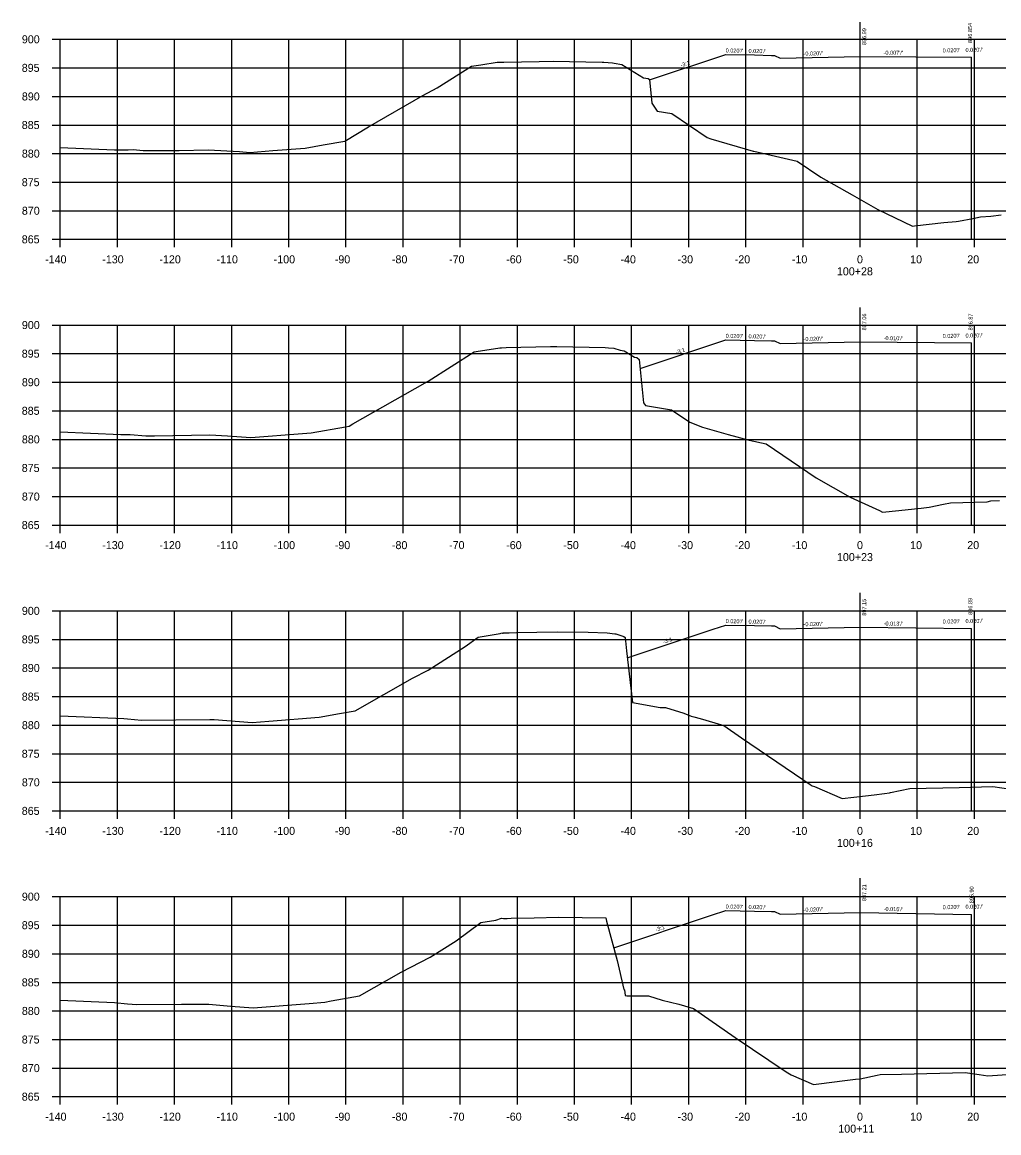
# Model space of a CAD drawing. Extents: x 1098669 to 1198896, y 698679 to 704410.
# Drawn here: x 1110744.5 to 1110915.5, y 704215.9 to 704410.2 of the extents above; entities that cross this region are included whole.
import ezdxf

# ---------------------------------------------------------------- set-up
doc = ezdxf.new("R2010")
doc.units = 0
for name, color, linetype in [('R_Axis', 7, 'Continuous'), ('R_Axis Annot', 7, 'Continuous'), ('R_Fin Surface', 7, 'Continuous'), ('R_Grid', 7, 'Continuous'), ('R_No Plot', 7, 'Continuous'), ('R_Xsect Elev', 7, 'Continuous'), ('R_Xsect Slope', 7, 'Continuous')]:
    doc.layers.add(name, color=color, linetype=linetype)

msp = doc.modelspace()

# ---------------------------------------------------------------- linework, layer by layer
at = {"layer": 'R_Axis'}
for p, q in [((1110749.8, 704407.22), (1110751.2, 704407.22)), ((1110751.2, 704372.22), (1110751.2, 704407.22)), ((1110749.8, 704402.22), (1110751.2, 704402.22)), ((1110749.8, 704397.22), (1110751.2, 704397.22)), ((1110749.8, 704392.22), (1110751.2, 704392.22)), ((1110749.8, 704387.22), (1110751.2, 704387.22)), ((1110749.8, 704382.22), (1110751.2, 704382.22)), ((1110749.8, 704377.22), (1110751.2, 704377.22)), ((1110749.8, 704372.22), (1110751.2, 704372.22)), ((1110751.2, 704372.22), (1111031.2, 704372.22)), ((1110751.2, 704370.82), (1110751.2, 704372.22)), ((1110761.2, 704370.82), (1110761.2, 704372.22)), ((1110771.2, 704370.82), (1110771.2, 704372.22)), ((1110781.2, 704370.82), (1110781.2, 704372.22)), ((1110791.2, 704370.82), (1110791.2, 704372.22)), ((1110801.2, 704370.82), (1110801.2, 704372.22)), ((1110811.2, 704370.82), (1110811.2, 704372.22)), ((1110821.2, 704370.82), (1110821.2, 704372.22)), ((1110831.2, 704370.82), (1110831.2, 704372.22)), ((1110841.2, 704370.82), (1110841.2, 704372.22)), ((1110851.2, 704370.82), (1110851.2, 704372.22)), ((1110861.2, 704370.82), (1110861.2, 704372.22)), ((1110871.2, 704370.82), (1110871.2, 704372.22)), ((1110881.2, 704370.82), (1110881.2, 704372.22)), ((1110891.2, 704370.82), (1110891.2, 704372.22)), ((1110901.2, 704370.82), (1110901.2, 704372.22)), ((1110911.2, 704370.82), (1110911.2, 704372.22)), ((1110749.8, 704357.22), (1110751.2, 704357.22)), ((1110751.2, 704322.22), (1110751.2, 704357.22)), ((1110749.8, 704352.22), (1110751.2, 704352.22)), ((1110749.8, 704347.22), (1110751.2, 704347.22)), ((1110749.8, 704342.22), (1110751.2, 704342.22)), ((1110749.8, 704337.22), (1110751.2, 704337.22)), ((1110749.8, 704332.22), (1110751.2, 704332.22)), ((1110749.8, 704327.22), (1110751.2, 704327.22)), ((1110749.8, 704322.22), (1110751.2, 704322.22)), ((1110751.2, 704322.22), (1111031.2, 704322.22)), ((1110751.2, 704320.82), (1110751.2, 704322.22)), ((1110761.2, 704320.82), (1110761.2, 704322.22)), ((1110771.2, 704320.82), (1110771.2, 704322.22)), ((1110781.2, 704320.82), (1110781.2, 704322.22)), ((1110791.2, 704320.82), (1110791.2, 704322.22)), ((1110801.2, 704320.82), (1110801.2, 704322.22)), ((1110811.2, 704320.82), (1110811.2, 704322.22)), ((1110821.2, 704320.82), (1110821.2, 704322.22)), ((1110831.2, 704320.82), (1110831.2, 704322.22)), ((1110841.2, 704320.82), (1110841.2, 704322.22)), ((1110851.2, 704320.82), (1110851.2, 704322.22)), ((1110861.2, 704320.82), (1110861.2, 704322.22)), ((1110871.2, 704320.82), (1110871.2, 704322.22)), ((1110881.2, 704320.82), (1110881.2, 704322.22)), ((1110891.2, 704320.82), (1110891.2, 704322.22)), ((1110901.2, 704320.82), (1110901.2, 704322.22)), ((1110911.2, 704320.82), (1110911.2, 704322.22)), ((1110749.8, 704307.22), (1110751.2, 704307.22)), ((1110751.2, 704272.22), (1110751.2, 704307.22)), ((1110749.8, 704302.22), (1110751.2, 704302.22)), ((1110749.8, 704297.22), (1110751.2, 704297.22)), ((1110749.8, 704292.22), (1110751.2, 704292.22)), ((1110749.8, 704287.22), (1110751.2, 704287.22)), ((1110749.8, 704282.22), (1110751.2, 704282.22)), ((1110749.8, 704277.22), (1110751.2, 704277.22)), ((1110749.8, 704272.22), (1110751.2, 704272.22)), ((1110751.2, 704272.22), (1111031.2, 704272.22)), ((1110751.2, 704270.82), (1110751.2, 704272.22)), ((1110761.2, 704270.82), (1110761.2, 704272.22)), ((1110771.2, 704270.82), (1110771.2, 704272.22)), ((1110781.2, 704270.82), (1110781.2, 704272.22)), ((1110791.2, 704270.82), (1110791.2, 704272.22)), ((1110801.2, 704270.82), (1110801.2, 704272.22)), ((1110811.2, 704270.82), (1110811.2, 704272.22)), ((1110821.2, 704270.82), (1110821.2, 704272.22)), ((1110831.2, 704270.82), (1110831.2, 704272.22)), ((1110841.2, 704270.82), (1110841.2, 704272.22)), ((1110851.2, 704270.82), (1110851.2, 704272.22)), ((1110861.2, 704270.82), (1110861.2, 704272.22)), ((1110871.2, 704270.82), (1110871.2, 704272.22)), ((1110881.2, 704270.82), (1110881.2, 704272.22)), ((1110891.2, 704270.82), (1110891.2, 704272.22)), ((1110901.2, 704270.82), (1110901.2, 704272.22)), ((1110911.2, 704270.82), (1110911.2, 704272.22)), ((1110749.8, 704257.22), (1110751.2, 704257.22)), ((1110751.2, 704222.22), (1110751.2, 704257.22)), ((1110749.8, 704252.22), (1110751.2, 704252.22)), ((1110749.8, 704247.22), (1110751.2, 704247.22)), ((1110749.8, 704242.22), (1110751.2, 704242.22)), ((1110749.8, 704237.22), (1110751.2, 704237.22)), ((1110749.8, 704232.22), (1110751.2, 704232.22)), ((1110749.8, 704227.22), (1110751.2, 704227.22)), ((1110749.8, 704222.22), (1110751.2, 704222.22)), ((1110751.2, 704222.22), (1111031.2, 704222.22)), ((1110751.2, 704220.82), (1110751.2, 704222.22)), ((1110761.2, 704220.82), (1110761.2, 704222.22)), ((1110771.2, 704220.82), (1110771.2, 704222.22)), ((1110781.2, 704220.82), (1110781.2, 704222.22)), ((1110791.2, 704220.82), (1110791.2, 704222.22)), ((1110801.2, 704220.82), (1110801.2, 704222.22)), ((1110811.2, 704220.82), (1110811.2, 704222.22)), ((1110821.2, 704220.82), (1110821.2, 704222.22)), ((1110831.2, 704220.82), (1110831.2, 704222.22)), ((1110841.2, 704220.82), (1110841.2, 704222.22)), ((1110851.2, 704220.82), (1110851.2, 704222.22)), ((1110861.2, 704220.82), (1110861.2, 704222.22)), ((1110871.2, 704220.82), (1110871.2, 704222.22)), ((1110881.2, 704220.82), (1110881.2, 704222.22)), ((1110891.2, 704220.82), (1110891.2, 704222.22)), ((1110901.2, 704220.82), (1110901.2, 704222.22)), ((1110911.2, 704220.82), (1110911.2, 704222.22))]:
    msp.add_line(p, q, dxfattribs=at)
at = {"layer": 'R_Fin Surface'}
for points in [[(1110854.34, 704400.12), (1110867.7, 704404.57), (1110872.7, 704404.47), (1110875.7, 704404.41), (1110876.2, 704404.41), (1110877.2, 704403.93), (1110891.2, 704404.21), (1110910.7, 704404.07)], [(1110852.68, 704349.63), (1110867.7, 704354.64), (1110872.7, 704354.54), (1110875.7, 704354.48), (1110876.2, 704354.48), (1110877.2, 704354), (1110891.2, 704354.28), (1110910.7, 704354.09)], [(1110850.43, 704298.98), (1110865.47, 704303.99), (1110867.7, 704304.73), (1110872.7, 704304.63), (1110875.7, 704304.57), (1110876.2, 704304.57), (1110877.2, 704304.09), (1110891.2, 704304.37), (1110910.7, 704304.11)], [(1110848.08, 704248.25), (1110865.18, 704253.95), (1110867.7, 704254.79), (1110872.7, 704254.69), (1110875.7, 704254.63), (1110876.2, 704254.63), (1110877.2, 704254.15), (1110891.2, 704254.43), (1110910.7, 704254.12)]]:
    msp.add_lwpolyline(points, dxfattribs=at)
at = {"layer": 'R_Grid'}
for p, q in [((1110751.2, 704407.22), (1111031.2, 704407.22)), ((1110751.2, 704372.22), (1110751.2, 704407.22)), ((1110761.2, 704372.22), (1110761.2, 704407.22)), ((1110771.2, 704372.22), (1110771.2, 704407.22)), ((1110781.2, 704372.22), (1110781.2, 704407.22)), ((1110791.2, 704372.22), (1110791.2, 704407.22)), ((1110801.2, 704372.22), (1110801.2, 704407.22)), ((1110811.2, 704372.22), (1110811.2, 704407.22)), ((1110821.2, 704372.22), (1110821.2, 704407.22)), ((1110831.2, 704372.22), (1110831.2, 704407.22)), ((1110841.2, 704372.22), (1110841.2, 704407.22)), ((1110851.2, 704372.22), (1110851.2, 704407.22)), ((1110861.2, 704372.22), (1110861.2, 704407.22)), ((1110871.2, 704372.22), (1110871.2, 704407.22)), ((1110881.2, 704372.22), (1110881.2, 704407.22)), ((1110891.2, 704372.22), (1110891.2, 704407.22)), ((1110901.2, 704372.22), (1110901.2, 704407.22)), ((1110911.2, 704372.22), (1110911.2, 704407.22)), ((1110910.7, 704372.22), (1110910.7, 704404.07)), ((1110751.2, 704402.22), (1111031.2, 704402.22)), ((1110751.2, 704397.22), (1111031.2, 704397.22)), ((1110751.2, 704392.22), (1111031.2, 704392.22)), ((1110751.2, 704387.22), (1111031.2, 704387.22)), ((1110751.2, 704382.22), (1111031.2, 704382.22)), ((1110751.2, 704377.22), (1111031.2, 704377.22)), ((1110751.2, 704372.22), (1111031.2, 704372.22)), ((1110751.2, 704357.22), (1111031.2, 704357.22)), ((1110751.2, 704322.22), (1110751.2, 704357.22)), ((1110761.2, 704322.22), (1110761.2, 704357.22)), ((1110771.2, 704322.22), (1110771.2, 704357.22)), ((1110781.2, 704322.22), (1110781.2, 704357.22)), ((1110791.2, 704322.22), (1110791.2, 704357.22)), ((1110801.2, 704322.22), (1110801.2, 704357.22)), ((1110811.2, 704322.22), (1110811.2, 704357.22)), ((1110821.2, 704322.22), (1110821.2, 704357.22)), ((1110831.2, 704322.22), (1110831.2, 704357.22)), ((1110841.2, 704322.22), (1110841.2, 704357.22)), ((1110851.2, 704322.22), (1110851.2, 704357.22)), ((1110861.2, 704322.22), (1110861.2, 704357.22)), ((1110871.2, 704322.22), (1110871.2, 704357.22)), ((1110881.2, 704322.22), (1110881.2, 704357.22)), ((1110891.2, 704322.22), (1110891.2, 704357.22)), ((1110901.2, 704322.22), (1110901.2, 704357.22)), ((1110911.2, 704322.22), (1110911.2, 704357.22)), ((1110910.7, 704322.22), (1110910.7, 704354.09)), ((1110751.2, 704352.22), (1111031.2, 704352.22)), ((1110751.2, 704347.22), (1111031.2, 704347.22)), ((1110751.2, 704342.22), (1111031.2, 704342.22)), ((1110751.2, 704337.22), (1111031.2, 704337.22)), ((1110751.2, 704332.22), (1111031.2, 704332.22)), ((1110751.2, 704327.22), (1111031.2, 704327.22)), ((1110751.2, 704322.22), (1111031.2, 704322.22)), ((1110751.2, 704307.22), (1111031.2, 704307.22)), ((1110751.2, 704272.22), (1110751.2, 704307.22)), ((1110761.2, 704272.22), (1110761.2, 704307.22)), ((1110771.2, 704272.22), (1110771.2, 704307.22)), ((1110781.2, 704272.22), (1110781.2, 704307.22)), ((1110791.2, 704272.22), (1110791.2, 704307.22)), ((1110801.2, 704272.22), (1110801.2, 704307.22)), ((1110811.2, 704272.22), (1110811.2, 704307.22)), ((1110821.2, 704272.22), (1110821.2, 704307.22)), ((1110831.2, 704272.22), (1110831.2, 704307.22)), ((1110841.2, 704272.22), (1110841.2, 704307.22)), ((1110851.2, 704272.22), (1110851.2, 704307.22)), ((1110861.2, 704272.22), (1110861.2, 704307.22)), ((1110871.2, 704272.22), (1110871.2, 704307.22)), ((1110881.2, 704272.22), (1110881.2, 704307.22)), ((1110891.2, 704272.22), (1110891.2, 704307.22)), ((1110901.2, 704272.22), (1110901.2, 704307.22)), ((1110911.2, 704272.22), (1110911.2, 704307.22)), ((1110910.7, 704272.22), (1110910.7, 704304.11)), ((1110751.2, 704302.22), (1111031.2, 704302.22)), ((1110751.2, 704297.22), (1111031.2, 704297.22)), ((1110751.2, 704292.22), (1111031.2, 704292.22)), ((1110751.2, 704287.22), (1111031.2, 704287.22)), ((1110751.2, 704282.22), (1111031.2, 704282.22)), ((1110751.2, 704277.22), (1111031.2, 704277.22)), ((1110751.2, 704272.22), (1111031.2, 704272.22)), ((1110751.2, 704257.22), (1111031.2, 704257.22)), ((1110751.2, 704222.22), (1110751.2, 704257.22)), ((1110761.2, 704222.22), (1110761.2, 704257.22)), ((1110771.2, 704222.22), (1110771.2, 704257.22)), ((1110781.2, 704222.22), (1110781.2, 704257.22)), ((1110791.2, 704222.22), (1110791.2, 704257.22)), ((1110801.2, 704222.22), (1110801.2, 704257.22)), ((1110811.2, 704222.22), (1110811.2, 704257.22)), ((1110821.2, 704222.22), (1110821.2, 704257.22)), ((1110831.2, 704222.22), (1110831.2, 704257.22)), ((1110841.2, 704222.22), (1110841.2, 704257.22)), ((1110851.2, 704222.22), (1110851.2, 704257.22)), ((1110861.2, 704222.22), (1110861.2, 704257.22)), ((1110871.2, 704222.22), (1110871.2, 704257.22)), ((1110881.2, 704222.22), (1110881.2, 704257.22)), ((1110891.2, 704222.22), (1110891.2, 704257.22)), ((1110901.2, 704222.22), (1110901.2, 704257.22)), ((1110911.2, 704222.22), (1110911.2, 704257.22)), ((1110910.7, 704222.22), (1110910.7, 704254.12)), ((1110751.2, 704252.22), (1111031.2, 704252.22)), ((1110751.2, 704247.22), (1111031.2, 704247.22)), ((1110751.2, 704242.22), (1111031.2, 704242.22)), ((1110751.2, 704237.22), (1111031.2, 704237.22)), ((1110751.2, 704232.22), (1111031.2, 704232.22)), ((1110751.2, 704227.22), (1111031.2, 704227.22)), ((1110751.2, 704222.22), (1111031.2, 704222.22))]:
    msp.add_line(p, q, dxfattribs=at)
at = {"layer": 'R_No Plot'}
for points in [[(1110751.2, 704388.29), (1110760.66, 704387.88), (1110763.05, 704387.89), (1110763.94, 704387.91), (1110765.7, 704387.75), (1110771.99, 704387.79), (1110777.06, 704387.88), (1110782.58, 704387.57), (1110784.38, 704387.43), (1110788.39, 704387.75), (1110794.05, 704388.19), (1110797.18, 704388.74), (1110800.97, 704389.38), (1110805.13, 704391.93), (1110814.67, 704397.37), (1110817.18, 704398.7), (1110823.14, 704402.5), (1110824.78, 704402.75), (1110827.67, 704403.21), (1110828.25, 704403.21), (1110828.84, 704403.24), (1110835.03, 704403.36), (1110837.49, 704403.4), (1110846.04, 704403.23), (1110846.29, 704403.23), (1110846.31, 704403.23), (1110847.86, 704403.11), (1110848.14, 704403.02), (1110849.49, 704402.83), (1110853.27, 704400.49), (1110854.09, 704400.38), (1110854.34, 704400.2), (1110854.73, 704396.04), (1110855.68, 704394.66), (1110858.21, 704394.26), (1110864.44, 704390.03), (1110865.06, 704389.8), (1110872.45, 704387.66), (1110872.56, 704387.63), (1110880.18, 704385.92), (1110884.3, 704383.12), (1110889.77, 704380.01), (1110894.29, 704377.43), (1110898.78, 704375.27), (1110900.33, 704374.54), (1110900.72, 704374.58), (1110905.84, 704375.15), (1110908.01, 704375.33), (1110908.4, 704375.38), (1110910.92, 704375.89), (1110912.26, 704376.16), (1110914.08, 704376.25), (1110915.86, 704376.49)], [(1110751.2, 704338.52), (1110761.8, 704338.06), (1110762.99, 704338.07), (1110763.43, 704338.08), (1110766.15, 704337.83), (1110767.66, 704337.84), (1110777.39, 704338.02), (1110780.49, 704337.84), (1110784.55, 704337.53), (1110793.6, 704338.25), (1110795.08, 704338.36), (1110801.14, 704339.43), (1110801.74, 704339.53), (1110802.4, 704339.93), (1110815.06, 704347.14), (1110815.57, 704347.42), (1110823.63, 704352.56), (1110824.01, 704352.61), (1110828.11, 704353.26), (1110828.39, 704353.26), (1110829.23, 704353.3), (1110837, 704353.45), (1110837.77, 704353.47), (1110838.11, 704353.46), (1110846.55, 704353.3), (1110847.13, 704353.22), (1110848.09, 704353.15), (1110849.21, 704352.8), (1110849.86, 704352.71), (1110851.69, 704351.58), (1110852.09, 704351.52), (1110852.53, 704351.19), (1110853.25, 704343.64), (1110853.61, 704343.12), (1110858.18, 704342.39), (1110861.37, 704340.23), (1110863.6, 704339.38), (1110868.08, 704338.08), (1110871.74, 704337.1), (1110874.74, 704336.43), (1110883.52, 704330.47), (1110889.44, 704327.09), (1110894.57, 704324.75), (1110895.13, 704324.48), (1110897.98, 704324.79), (1110900.72, 704325.09), (1110901.88, 704325.18), (1110903.3, 704325.38), (1110905.8, 704325.88), (1110907.02, 704326.14), (1110913.4, 704326.3), (1110914.07, 704326.47), (1110915.58, 704326.54)], [(1110751.2, 704288.86), (1110762.31, 704288.37), (1110762.94, 704288.31), (1110765.41, 704288.12), (1110777.37, 704288.21), (1110777.77, 704288.2), (1110778.1, 704288.18), (1110784.79, 704287.66), (1110787.72, 704287.89), (1110796.5, 704288.6), (1110800.09, 704289.23), (1110802.8, 704289.72), (1110812.86, 704295.45), (1110815.58, 704296.83), (1110822.05, 704300.96), (1110824.31, 704302.63), (1110828.19, 704303.25), (1110828.49, 704303.35), (1110828.59, 704303.34), (1110828.71, 704303.34), (1110828.79, 704303.35), (1110829.76, 704303.39), (1110831.03, 704303.41), (1110838.15, 704303.55), (1110843.58, 704303.47), (1110846.9, 704303.4), (1110848.26, 704303.21), (1110848.41, 704303.2), (1110849.13, 704302.97), (1110849.84, 704302.71), (1110850.07, 704302.55), (1110850.29, 704300.23), (1110851.34, 704291.18), (1110856.2, 704290.29), (1110857.15, 704290.29), (1110860.32, 704289.3), (1110861.62, 704288.8), (1110862.09, 704288.67), (1110863.19, 704288.37), (1110867.31, 704287.13), (1110870.41, 704284.99), (1110881.15, 704277.72), (1110882.46, 704276.84), (1110882.82, 704276.63), (1110883.19, 704276.46), (1110888.03, 704274.41), (1110892.1, 704274.84), (1110893.67, 704275.02), (1110895.43, 704275.25), (1110896.34, 704275.37), (1110896.53, 704275.41), (1110899.86, 704276.11), (1110908.53, 704276.33), (1110914.39, 704276.47), (1110917.59, 704276)], [(1110751.2, 704239.12), (1110760.7, 704238.71), (1110762.97, 704238.49), (1110764.59, 704238.36), (1110772.42, 704238.42), (1110777.19, 704238.4), (1110781.04, 704238.05), (1110784.96, 704237.75), (1110794.74, 704238.54), (1110797.5, 704238.76), (1110798.62, 704238.96), (1110803.54, 704239.86), (1110810.85, 704244.02), (1110815.95, 704246.61), (1110820.47, 704249.5), (1110824.79, 704252.69), (1110827.44, 704253.11), (1110828.42, 704253.44), (1110828.76, 704253.39), (1110829.13, 704253.39), (1110829.41, 704253.42), (1110830.13, 704253.45), (1110834.16, 704253.53), (1110838.42, 704253.61), (1110846.7, 704253.48), (1110846.82, 704252.92), (1110848.68, 704246.04), (1110849.85, 704240.96), (1110849.95, 704240.89), (1110850.07, 704239.9), (1110850.37, 704239.85), (1110854.13, 704239.85), (1110856.56, 704239.09), (1110859.46, 704238.41), (1110862.05, 704237.63), (1110869.34, 704232.6), (1110878.23, 704226.59), (1110879.13, 704226.03), (1110883.03, 704224.35), (1110883.94, 704224.49), (1110888.52, 704225.03), (1110890.37, 704225.27), (1110891.22, 704225.33), (1110894.18, 704225.96), (1110894.71, 704226.09), (1110898.45, 704226.17), (1110909.56, 704226.44), (1110912.05, 704226.08), (1110913.54, 704225.87), (1110921.08, 704226.4)]]:
    msp.add_lwpolyline(points, dxfattribs=at)
at = {"layer": 'R_Xsect Elev'}
for p, q in [((1110891.2, 704404.21), (1110891.2, 704410.21)), ((1110891.2, 704354.28), (1110891.2, 704360.28)), ((1110891.2, 704304.37), (1110891.2, 704310.37)), ((1110891.2, 704254.43), (1110891.2, 704260.43))]:
    msp.add_line(p, q, dxfattribs=at)

# ---------------------------------------------------------------- texts
at = {"layer": 'R_Axis Annot'}
for s, p in [('900', (1110744.47, 704406.52)), ('895', (1110744.45, 704401.52)), ('890', (1110744.47, 704396.52)), ('885', (1110744.45, 704391.52)), ('880', (1110744.47, 704386.52)), ('875', (1110744.45, 704381.52)), ('870', (1110744.47, 704376.52)), ('865', (1110744.45, 704371.52)), ('-140', (1110748.54, 704368.02)), ('-130', (1110758.54, 704368.02)), ('-120', (1110768.54, 704368.02)), ('-110', (1110778.54, 704368.02)), ('-100', (1110788.54, 704368.02)), ('-90', (1110799.24, 704368.02)), ('-80', (1110809.24, 704368.02)), ('-70', (1110819.24, 704368.02)), ('-60', (1110829.24, 704368.02)), ('-50', (1110839.24, 704368.02)), ('-40', (1110849.24, 704368.02)), ('-30', (1110859.24, 704368.02)), ('-20', (1110869.24, 704368.02)), ('-10', (1110879.24, 704368.02)), ('0', (1110890.64, 704368.02)), ('10', (1110899.94, 704368.02)), ('20', (1110909.94, 704368.02)), ('100+28', (1110887.12, 704365.92)), ('900', (1110744.47, 704356.52)), ('895', (1110744.45, 704351.52)), ('890', (1110744.47, 704346.52)), ('885', (1110744.45, 704341.52)), ('880', (1110744.47, 704336.52)), ('875', (1110744.45, 704331.52)), ('870', (1110744.47, 704326.52)), ('865', (1110744.45, 704321.52)), ('-140', (1110748.54, 704318.02)), ('-130', (1110758.54, 704318.02)), ('-120', (1110768.54, 704318.02)), ('-110', (1110778.54, 704318.02)), ('-100', (1110788.54, 704318.02)), ('-90', (1110799.24, 704318.02)), ('-80', (1110809.24, 704318.02)), ('-70', (1110819.24, 704318.02)), ('-60', (1110829.24, 704318.02)), ('-50', (1110839.24, 704318.02)), ('-40', (1110849.24, 704318.02)), ('-30', (1110859.24, 704318.02)), ('-20', (1110869.24, 704318.02)), ('-10', (1110879.24, 704318.02)), ('0', (1110890.64, 704318.02)), ('10', (1110899.94, 704318.02)), ('20', (1110909.94, 704318.02)), ('100+23', (1110887.13, 704315.92)), ('900', (1110744.47, 704306.52)), ('895', (1110744.45, 704301.52)), ('890', (1110744.47, 704296.52)), ('885', (1110744.45, 704291.52)), ('880', (1110744.47, 704286.52)), ('875', (1110744.45, 704281.52)), ('870', (1110744.47, 704276.52)), ('865', (1110744.45, 704271.52)), ('-140', (1110748.54, 704268.02)), ('-130', (1110758.54, 704268.02)), ('-120', (1110768.54, 704268.02)), ('-110', (1110778.54, 704268.02)), ('-100', (1110788.54, 704268.02)), ('-90', (1110799.24, 704268.02)), ('-80', (1110809.24, 704268.02)), ('-70', (1110819.24, 704268.02)), ('-60', (1110829.24, 704268.02)), ('-50', (1110839.24, 704268.02)), ('-40', (1110849.24, 704268.02)), ('-30', (1110859.24, 704268.02)), ('-20', (1110869.24, 704268.02)), ('-10', (1110879.24, 704268.02)), ('0', (1110890.64, 704268.02)), ('10', (1110899.94, 704268.02)), ('20', (1110909.94, 704268.02)), ('100+16', (1110887.12, 704265.92)), ('900', (1110744.47, 704256.52)), ('895', (1110744.45, 704251.52)), ('890', (1110744.47, 704246.52)), ('885', (1110744.45, 704241.52)), ('880', (1110744.47, 704236.52)), ('875', (1110744.45, 704231.52)), ('870', (1110744.47, 704226.52)), ('865', (1110744.45, 704221.52)), ('-140', (1110748.54, 704218.02)), ('-130', (1110758.54, 704218.02)), ('-120', (1110768.54, 704218.02)), ('-110', (1110778.54, 704218.02)), ('-100', (1110788.54, 704218.02)), ('-90', (1110799.24, 704218.02)), ('-80', (1110809.24, 704218.02)), ('-70', (1110819.24, 704218.02)), ('-60', (1110829.24, 704218.02)), ('-50', (1110839.24, 704218.02)), ('-40', (1110849.24, 704218.02)), ('-30', (1110859.24, 704218.02)), ('-20', (1110869.24, 704218.02)), ('-10', (1110879.24, 704218.02)), ('0', (1110890.64, 704218.02)), ('10', (1110899.94, 704218.02)), ('20', (1110909.94, 704218.02)), ('100+11', (1110887.37, 704215.92))]:
    msp.add_text(s, height=1.4, dxfattribs=at).set_placement(p)
at = {"layer": 'R_Xsect Elev'}
for s, p in [('896.854', (1110910.78, 704406.59)), ('896.99', (1110892.25, 704406.21)), ('897.06', (1110892.25, 704356.28)), ('896.87', (1110910.86, 704356.28)), ('897.15', (1110892.25, 704306.37)), ('896.89', (1110910.82, 704306.52)), ('897.21', (1110892.25, 704256.43)), ('896.90', (1110911.06, 704256.05))]:
    msp.add_text(s, height=0.7, rotation=90, dxfattribs=at).set_placement(p)
at = {"layer": 'R_Xsect Slope'}
for s, rotation, p in [("0.020'/'", 358.8542, (1110867.65, 704404.92)), ("0.020'/'", 358.8542, (1110871.65, 704404.84)), ("0.020'/'", 1.1458, (1110905.64, 704404.92)), ("0.020'/'", 1.1458, (1110909.64, 704405)), ('-3:1', 18.4349, (1110859.87, 704402.31)), ("-0.020'/'", 1.1458, (1110881.29, 704404.36)), ("-0.007'/'", 359.6092, (1110895.29, 704404.53)), ("0.020'/'", 358.8542, (1110867.65, 704354.99)), ("0.020'/'", 358.8542, (1110871.65, 704354.91)), ("-0.020'/'", 1.1458, (1110881.29, 704354.43)), ("-0.010'/'", 359.4518, (1110895.3, 704354.59)), ("0.020'/'", 1.1458, (1110905.64, 704354.95)), ("0.020'/'", 1.1458, (1110909.64, 704355.03)), ('-3:1', 18.4349, (1110859.04, 704352.1)), ("0.020'/'", 358.8542, (1110867.65, 704305.08)), ("0.020'/'", 358.8542, (1110871.65, 704305)), ("-0.020'/'", 1.1458, (1110881.29, 704304.52)), ("-0.013'/'", 359.2367, (1110895.3, 704304.66)), ("0.020'/'", 1.1458, (1110905.64, 704304.99)), ("0.020'/'", 1.1458, (1110909.64, 704305.07)), ('-3:1', 18.434, (1110856.8, 704301.45)), ("0.020'/'", 358.8542, (1110867.65, 704255.14)), ("0.020'/'", 358.8542, (1110871.65, 704255.06)), ("0.020'/'", 1.1458, (1110905.64, 704255.01)), ("0.020'/'", 1.1458, (1110909.64, 704255.09)), ("-0.020'/'", 1.1458, (1110881.29, 704254.58)), ("-0.016'/'", 359.0846, (1110895.3, 704254.71)), ('-3:1', 18.4341, (1110855.48, 704251.07))]:
    msp.add_text(s, height=0.7, rotation=rotation, dxfattribs=at).set_placement(p)

doc.saveas('drawing.dxf')
